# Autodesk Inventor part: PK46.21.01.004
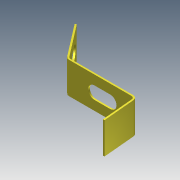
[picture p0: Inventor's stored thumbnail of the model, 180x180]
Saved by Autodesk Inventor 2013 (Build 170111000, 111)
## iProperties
Created: 2005-04
Part Number: PK46.21.01.004
Material: Steel, Mild
Document SubType Name: Sheet Metal
Designer: salex
Manufacturer: Standard
Standards Organization: Custom
Density: 7.86 g/cm^3
Sheet Metal Rule: Default
Author: salex
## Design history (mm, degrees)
node "ФлнОтгиб1"
sketch "Sketch2"
  geometry: L1 (161.943, 60)-(261.943, 60); L2 (261.943, 140)-(161.943, 140); L3 (0, 200)-(0, 0) reference; L4 (0, 0)-(396.943, 0) reference; L5 (396.943, 0)-(396.943, 200) reference; A1 r 40 centre (161.943, 100) between (161.943, 140) and (161.943, 60); A2 r 40 centre (261.943, 100) between (261.943, 60) and (261.943, 140); 1 further point
  constraints: 4 end point, 4 point on circle, 4 tangent, 2 centre point, 1 horizontal, 1 parallel
  dimensions: "d16" = 100 distance of A2.centre A1.centre; "d17" = 40 radius of A1; "d19" = 200 distance of L3.start L3.end (derived); "d20" = 100 distance from line of A1.centre L4 (= 0.5 x d19); "d23" = 135 distance from line of A2.centre L5
cut "Cut1" sketch "Sketch2" dims "d21" = 10 (= Thickness), "d22" = 0
sketch "Sketch3"
  geometry: L1 (60, -78.841)-(60, -138.841); L2 (140, -138.841)-(140, -78.841); L3 (0, 0)-(200, 0) reference; L4 (200, -256.224)-(200, 0) reference; A1 r 40 centre (100, -78.841) between (140, -78.841) and (60, -78.841); A2 r 40 centre (100, -138.841) between (60, -138.841) and (140, -138.841); 1 further point
  constraints: 4 end point, 4 point on circle, 4 tangent, 2 centre point, 1 parallel
  dimensions: "d24" = 60 distance of A2.centre A1.centre; "d25" = 40 radius of A1; "d26" = 78.84052 distance from line of A1.centre L3; "d27" = 100 distance from line of A1.centre L4 (= d20)
cut "Cut2" sketch "Sketch3" dims "d28" = 10 (= Thickness), "d29" = 0
body "Solid1"
sketch "Эскиз1"
  geometry: L1 (-165, 215)-(0, 0); L2 (0, 0)-(430, 0); L3 (430, 0)-(450, -220)
  constraints: 6 end point, 1 horizontal, 1 other
  dimensions: "d4" = 430 distance of L1.end L2.end; "d12" = 165 horizontal distance of L1.start L1.end; "d13" = 215 vertical distance of L1.start L1.end; "d14" = 220 vertical distance of L2.end L3.end; "d15" = 615 horizontal distance of L3.end L1.start
feature "Плакирование1" dims "d5" = 200, "d6" = 10 (= BendReliefWidth), "d8" = 20 (= MinimumRemnant), "d10" = 20 (= BendRadius), "d11" = 10, "Thickness" = 10
feature "Изгиб1" dims "d6" = 10 (= BendReliefWidth), "d7" = 5 (= BendReliefDepth), "d8" = 20 (= MinimumRemnant), "d9" = 20 (= BendRadius), "d10" = 20 (= BendRadius), "d11" = 10, "SeamGap" = 0.01, "Thickness" = 10
other parameters: "BendRadius" = 20, "BendReliefDepth" = 5 (= 0.5 x Thickness)
